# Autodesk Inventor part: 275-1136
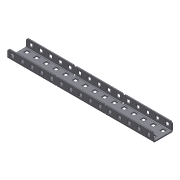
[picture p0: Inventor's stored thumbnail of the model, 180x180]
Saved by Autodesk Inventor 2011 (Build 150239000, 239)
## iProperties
Company: Autodesk Inc.
Created: 2005-08
Part Number: 275-1136
Document SubType Name: Sheet Metal
Designer: Autodesk Inc.
Density: 1 g/cm^3
Sheet Metal Rule: Default
Sheet Metal Width: 0.000 in
Sheet Metal Length: 0.000 in
Sheet Metal Area: 0.000 in^2
Catalog Web Link: http://www.vexrobotics.com/products/accessories/structure/c-channel.html
Description: VEX C-channel has holes on 0.500" increments. This structural member is perfect for building bigger robots. Excellent strength
Vendor: Innovation First, Inc.
Author: Autodesk Inc.
Title: VEX Robotics Kit of Parts
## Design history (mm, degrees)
node "Face1"
  sketch "Sketch1"
    geometry: L1 (-38.442, 14.458)-(148.248, 14.458); L2 (150.153, 12.553)-(150.153, 3.028); L3 (150.153, 3.028)-(-40.347, 3.028); L4 (-40.347, 3.028)-(-40.347, 12.553); L5 (-40.347, 12.553)-(-38.442, 14.458); L6 (148.248, 14.458)-(150.153, 12.553); 2 further points
    constraints: 16 end point, 4 point on line, 2 parallel, 1 horizontal, 1 perpendicular
    dimensions: "d5" = 11.43 distance of L3.end point (-40.347, 14.458); "d64" = 190.5 distance of L2.end L3.end; "d98" = 1.905 distance of L4.end point (-40.347, 14.458); "d99" = 1.905 distance of L1.start point (-40.347, 14.458) (= d98); "d102" = 1.905 distance of L1.end point (150.153, 14.458); "d103" = 1.905 distance of L2.start point (150.153, 14.458) (= d102)
node "Flange3"
sketch "Sketch10" dims "d134" = 25.4
  geometry: L1 (0, 0)-(0, 10.566) reference; L2 (0, 13.589)-(0, 9.779); L3 (0, 9.779)-(1.905, 11.684); L4 (1.905, 11.684)-(0, 13.589); L5 (190.5, 10.566)-(0, 10.566) reference; L6 (0, 13.589)-(-1.905, 11.684); L7 (-1.905, 11.684)-(0, 9.779); L8 (63.5, 13.589)-(61.595, 11.684); L9 (61.595, 11.684)-(63.5, 9.779); L10 (65.405, 11.684)-(63.5, 13.589); L11 (63.5, 9.779)-(65.405, 11.684); L12 (127, 13.589)-(125.095, 11.684); L13 (125.095, 11.684)-(127, 9.779); L14 (128.905, 11.684)-(127, 13.589); L15 (127, 9.779)-(128.905, 11.684); 1 further point
  constraints: 26 end point, 2 parallel, 1 collinear, 1 horizontal, 1 perpendicular, 1 point on line, 16 other
  dimensions: "d124" = 3.81 distance of L2.start L2.end; "d127" = 1.905 distance from line of L2 L3.end; "d131" = 63.5 distance of L2.start L8.start; "d160" = 1.1176 distance from line of L6.end L5
cut "Cut5" sketch "Sketch10" dims "d125" = 1.27 (= Thickness), "d126" = 0
sketch "Sketch11" dims "d143" = 25.4
  geometry: L1 (0, 0)-(186.69, 0) reference; L2 (-1.905, -9.296)-(-1.905, -1.905) reference; L3 (59.69, 0)-(61.595, -1.905); L4 (61.595, -1.905)-(63.5, 0); L5 (63.5, 0)-(61.595, 1.905); L6 (61.595, 1.905)-(59.69, 0); L7 (125.095, -1.905)-(127, 0); L8 (127, 0)-(125.095, 1.905); L9 (125.095, 1.905)-(123.19, 0); L10 (123.19, 0)-(125.095, -1.905); 1 further point
  constraints: 16 end point, 2 parallel, 2 perpendicular, 2 point on line, 1 horizontal, 8 other
  dimensions: "d136" = 1.905 horizontal distance of L5.end L3.start; "d137" = 63.5 distance from line of L5.end L2; "d140" = 63.5 distance of L4.end L7.end
cut "Cut6" sketch "Sketch11" dims "d145" = 1.27 (= Thickness), "d146" = 0
sketch "Sketch12" dims "d156" = 25.4
  geometry: L1 (1.905, 9.296)-(61.595, 9.296) reference; L2 (0, 0)-(0, 7.391) reference; L3 (4.064, 6.502)-(8.636, 6.502); L4 (8.636, 6.502)-(8.636, 1.93); L5 (8.636, 1.93)-(4.064, 1.93); L6 (4.064, 1.93)-(4.064, 6.502); L7 (16.764, 6.502)-(21.336, 6.502); L8 (21.336, 6.502)-(21.336, 1.93); L9 (21.336, 1.93)-(16.764, 1.93); L10 (16.764, 1.93)-(16.764, 6.502); L11 (29.464, 6.502)-(34.036, 6.502); L12 (34.036, 6.502)-(34.036, 1.93); L13 (34.036, 1.93)-(29.464, 1.93); L14 (29.464, 1.93)-(29.464, 6.502); L15 (42.164, 6.502)-(46.736, 6.502); L16 (46.736, 6.502)-(46.736, 1.93); L17 (46.736, 1.93)-(42.164, 1.93); L18 (42.164, 1.93)-(42.164, 6.502); L19 (54.864, 6.502)-(59.436, 6.502); L20 (59.436, 6.502)-(59.436, 1.93); L21 (59.436, 1.93)-(54.864, 1.93); L22 (54.864, 1.93)-(54.864, 6.502); L23 (67.564, 6.502)-(72.136, 6.502); L24 (72.136, 6.502)-(72.136, 1.93); L25 (72.136, 1.93)-(67.564, 1.93); L26 (67.564, 1.93)-(67.564, 6.502); L27 (80.264, 6.502)-(84.836, 6.502); L28 (84.836, 6.502)-(84.836, 1.93); L29 (84.836, 1.93)-(80.264, 1.93); L30 (80.264, 1.93)-(80.264, 6.502); L31 (92.964, 6.502)-(97.536, 6.502); L32 (97.536, 6.502)-(97.536, 1.93); L33 (97.536, 1.93)-(92.964, 1.93); L34 (92.964, 1.93)-(92.964, 6.502); L35 (105.664, 6.502)-(110.236, 6.502); L36 (110.236, 6.502)-(110.236, 1.93); L37 (110.236, 1.93)-(105.664, 1.93); L38 (105.664, 1.93)-(105.664, 6.502); L39 (118.364, 6.502)-(122.936, 6.502); L40 (122.936, 6.502)-(122.936, 1.93); L41 (122.936, 1.93)-(118.364, 1.93); L42 (118.364, 1.93)-(118.364, 6.502); L43 (131.064, 6.502)-(135.636, 6.502); L44 (135.636, 6.502)-(135.636, 1.93); L45 (135.636, 1.93)-(131.064, 1.93); L46 (131.064, 1.93)-(131.064, 6.502); L47 (143.764, 6.502)-(148.336, 6.502); L48 (148.336, 6.502)-(148.336, 1.93); L49 (148.336, 1.93)-(143.764, 1.93); L50 (143.764, 1.93)-(143.764, 6.502); L51 (156.464, 6.502)-(161.036, 6.502); L52 (161.036, 6.502)-(161.036, 1.93); L53 (161.036, 1.93)-(156.464, 1.93); L54 (156.464, 1.93)-(156.464, 6.502); L55 (169.164, 6.502)-(173.736, 6.502); L56 (173.736, 6.502)-(173.736, 1.93); L57 (173.736, 1.93)-(169.164, 1.93); L58 (169.164, 1.93)-(169.164, 6.502); L59 (181.864, 6.502)-(186.436, 6.502); L60 (186.436, 6.502)-(186.436, 1.93); L61 (186.436, 1.93)-(181.864, 1.93); L62 (181.864, 1.93)-(181.864, 6.502)
  constraints: 120 end point, 2 horizontal, 2 parallel, 1 perpendicular, 112 other
  dimensions: "d147" = 2.794 distance between parallel lines of L1 L3; "d148" = 4.572 distance of L5.end L3.start; "d149" = 4.572 distance of L3.start L3.end; "d150" = 4.064 distance between parallel lines of L2 L6; "d153" = 12.7 distance of L3.start L7.start
cut "Cut7" sketch "Sketch12" dims "d158" = 1.27 (= Thickness), "d159" = 0
sketch "Sketch13" dims "d180" = 25.4
  geometry: L1 (62.713, 10.566)-(0, 10.566) reference; L2 (0, 0)-(0, 10.566) reference; L3 (4.064, 8.636)-(8.636, 8.636); L4 (8.636, 8.636)-(8.636, 4.064); L5 (8.636, 4.064)-(4.064, 4.064); L6 (4.064, 4.064)-(4.064, 8.636); L7 (0, 11.43)-(62.712, 11.43) reference; L8 (16.764, 8.636)-(21.336, 8.636); L9 (21.336, 4.064)-(16.764, 4.064); L10 (16.764, 4.064)-(16.764, 8.636); L11 (21.336, 8.636)-(21.336, 4.064); L12 (29.464, 8.636)-(34.036, 8.636); L13 (34.036, 4.064)-(29.464, 4.064); L14 (29.464, 4.064)-(29.464, 8.636); L15 (34.036, 8.636)-(34.036, 4.064); L16 (42.164, 8.636)-(46.736, 8.636); L17 (46.736, 4.064)-(42.164, 4.064); L18 (42.164, 4.064)-(42.164, 8.636); L19 (46.736, 8.636)-(46.736, 4.064); L20 (54.864, 8.636)-(59.436, 8.636); L21 (59.436, 4.064)-(54.864, 4.064); L22 (54.864, 4.064)-(54.864, 8.636); L23 (59.436, 8.636)-(59.436, 4.064); L24 (67.564, 8.636)-(72.136, 8.636); L25 (72.136, 4.064)-(67.564, 4.064); L26 (67.564, 4.064)-(67.564, 8.636); L27 (72.136, 8.636)-(72.136, 4.064); L28 (80.264, 8.636)-(84.836, 8.636); L29 (84.836, 4.064)-(80.264, 4.064); L30 (80.264, 4.064)-(80.264, 8.636); L31 (84.836, 8.636)-(84.836, 4.064); L32 (92.964, 8.636)-(97.536, 8.636); L33 (97.536, 4.064)-(92.964, 4.064); L34 (92.964, 4.064)-(92.964, 8.636); L35 (97.536, 8.636)-(97.536, 4.064); L36 (105.664, 8.636)-(110.236, 8.636); L37 (110.236, 4.064)-(105.664, 4.064); L38 (105.664, 4.064)-(105.664, 8.636); L39 (110.236, 8.636)-(110.236, 4.064); L40 (118.364, 8.636)-(122.936, 8.636); L41 (122.936, 4.064)-(118.364, 4.064); L42 (118.364, 4.064)-(118.364, 8.636); L43 (122.936, 8.636)-(122.936, 4.064); L44 (131.064, 8.636)-(135.636, 8.636); L45 (135.636, 4.064)-(131.064, 4.064); L46 (131.064, 4.064)-(131.064, 8.636); L47 (135.636, 8.636)-(135.636, 4.064); L48 (143.764, 8.636)-(148.336, 8.636); L49 (148.336, 4.064)-(143.764, 4.064); L50 (143.764, 4.064)-(143.764, 8.636); L51 (148.336, 8.636)-(148.336, 4.064); L52 (156.464, 8.636)-(161.036, 8.636); L53 (161.036, 4.064)-(156.464, 4.064); L54 (156.464, 4.064)-(156.464, 8.636); L55 (161.036, 8.636)-(161.036, 4.064); L56 (169.164, 8.636)-(173.736, 8.636); L57 (173.736, 4.064)-(169.164, 4.064); L58 (169.164, 4.064)-(169.164, 8.636); L59 (173.736, 8.636)-(173.736, 4.064); L60 (181.864, 8.636)-(186.436, 8.636); L61 (186.436, 4.064)-(181.864, 4.064); L62 (181.864, 4.064)-(181.864, 8.636); L63 (186.436, 8.636)-(186.436, 4.064); 1 further point
  constraints: 120 end point, 2 horizontal, 2 parallel, 1 perpendicular, 112 other
  dimensions: "d161" = 4.064 distance between parallel lines of L2 L6; "d162" = 4.572 distance of L5.end L3.start; "d163" = 4.572 distance of L4.end L5.end; "d164" = 2.794 distance between parallel lines of L7 L3; "d177" = 12.7 distance of L3.start L8.start
cut "Cut8" sketch "Sketch13" dims "d173" = 1.27 (= Thickness), "d174" = 0
mirror "Mirror1"
body "Solid1"
face "Plate1" dims "Thickness" = 1.27
sketch "Sketch8"
  geometry: L1 (0, 12.7)-(-190.5, 12.7); L2 (-190.5, 12.7)-(-190.5, 0); 2 other entities
  constraints: 4 end point, 4 other
face "Plate4" dims "d107" = 1.27 (= BendReliefWidth), "d108" = 0.635 (= BendReliefDepth), "d109" = 2.54 (= MinimumRemnant), "d110" = 0.8636 (= BendRadius), "d111" = 12.7, "d112" = 90 deg, "d113" = 0.8636 (= BendRadius), "d114" = 5.08 (= CornerReliefSize), "d115" = 1.27 (= GapSize), "d116" = 1.27 (= JacobiRadiusSize), "SeamGap" = 0.00508, "Thickness" = 1.27
bend "Bend3" dims "d107" = 1.27 (= BendReliefWidth), "d108" = 0.635 (= BendReliefDepth), "d109" = 2.54 (= MinimumRemnant), "d110" = 0.8636 (= BendRadius), "d111" = 12.7, "d112" = 90 deg, "d113" = 0.8636 (= BendRadius), "SeamGap" = 0.00508, "Thickness" = 1.27
feature "Corner2" dims "d111" = 12.7, "d112" = 90 deg, "d114" = 5.08 (= CornerReliefSize), "d115" = 1.27 (= GapSize), "d116" = 1.27 (= JacobiRadiusSize)
other parameters: "BendRadius" = 0.8636, "BendReliefWidth" = 1.27 (= Thickness), "BendReliefDepth" = 0.635 (= 0.5 x Thickness), "CornerReliefSize" = 5.08 (= 4 x Thickness), "MinimumRemnant" = 2.54 (= 2 x Thickness), "TransitionRadius" = 0.8636 (= BendRadius), "d14" = 0.8636 (= BendRadius), "JacobiRadiusSize" = 1.27 (= Thickness), "GapSize" = 1.27 (= Thickness)
